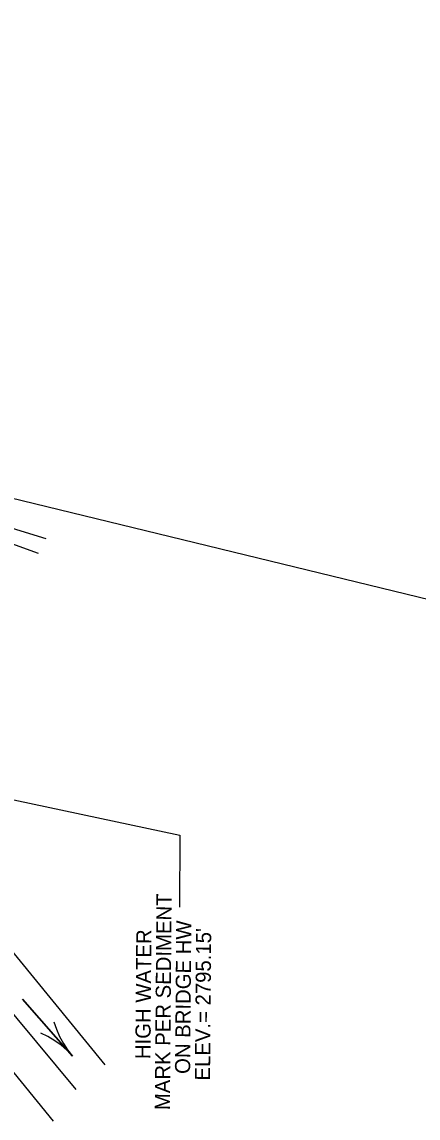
# Model space of a CAD drawing. Extents: x 1088366 to 1089341, y 781245 to 782648.
# Drawn here: x 1088931.9 to 1089036.3, y 781554.6 to 781843.2 of the extents above; entities that cross this region are included whole.
import ezdxf

# ---------------------------------------------------------------- set-up
doc = ezdxf.new("R2010")
doc.units = 0
for name, color, linetype in [('Exist DTM Spot Elevation Leader', 7, 'Continuous'), ('Exist DTM Spot Elevation Text', 7, 'Continuous'), ('Exist Hydro Jurisdictional Stream or Body of Water', 7, 'Continuous'), ('Exist Hydro River Flow Arrow CELL', 7, 'Continuous'), ('Exist Property Line', 7, 'Continuous'), ('Exist Roads Soil', 7, 'Continuous'), ('Exist Vegetation Woods Line', 7, 'Continuous')]:
    doc.layers.add(name, color=color, linetype=linetype)

msp = doc.modelspace()

# ---------------------------------------------------------------- linework, layer by layer
at = {"layer": 'Exist DTM Spot Elevation Leader'}
msp.add_lwpolyline([(1088869.43, 781651.14), (1088973.58, 781629.08), (1088973.42, 781610.13)], dxfattribs=at)
at = {"layer": 'Exist Hydro Jurisdictional Stream or Body of Water'}
for points in [[(1088953.84, 781568.58), (1088926.46, 781602.12), (1088911.94, 781623.53), (1088894.24, 781650), (1088883.33, 781666.95), (1088869.26, 781670.6), (1088867.16, 781672.95)], [(1088946.2, 781562.04), (1088920.23, 781593.24), (1088897.39, 781620.42), (1088884.95, 781640.8), (1088873.35, 781653.24), (1088866.79, 781656.11)]]:
    msp.add_lwpolyline(points, dxfattribs=at)
at = {"layer": 'Exist Hydro River Flow Arrow CELL'}
msp.add_line((1088938.67, 781578.4), (1088938.67, 781578.4), dxfattribs=at)
msp.add_lwpolyline([(1088940.38, 781579.91), (1088941.04, 781577.97), (1088941.87, 781576.07), (1088942.86, 781574.22), (1088943.98, 781572.48), (1088945.28, 781570.89), (1088932.06, 781585.9), (1088945.28, 781570.89), (1088943.87, 781572.38), (1088942.28, 781573.71), (1088940.57, 781574.93), (1088938.79, 781575.99), (1088936.95, 781576.88)], dxfattribs=at)
at = {"layer": 'Exist Property Line'}
msp.add_line((1088887.78, 781727.92), (1089277.34, 781633.17), dxfattribs=at)
at = {"layer": 'Exist Roads Soil'}
msp.add_lwpolyline([(1088936.3, 781703.23), (1088910.86, 781712.46), (1088894.35, 781716.45), (1088880.49, 781722.78), (1088873.17, 781728.87), (1088868.09, 781739.51)], dxfattribs=at)
at = {"layer": 'Exist Vegetation Woods Line'}
for points in [[(1088938.32, 781707.06), (1088898.21, 781719.36), (1088881.24, 781725.94), (1088868.09, 781739.51), (1088882.14, 781907.48)], [(1088992.73, 781306.05), (1088897.1, 781404.36), (1088893.35, 781443.24), (1088904.2, 781521.06), (1088876.71, 781575.21), (1088876.03, 781632.36), (1088940.16, 781553.71)]]:
    msp.add_lwpolyline(points, dxfattribs=at)

# ---------------------------------------------------------------- texts
at = {"layer": 'Exist DTM Spot Elevation Text'}
for s, p in [('MARK PER SEDIMENT', (1088970.93, 781556.63)), ('ON BRIDGE HW', (1088976.26, 781566.16)), ('HIGH WATER', (1088965.79, 781570.06)), ("ELEV.= 2795.15'", (1088981.5, 781564.42))]:
    msp.add_text(s, height=4, rotation=89.533, dxfattribs=at).set_placement(p)

doc.saveas('drawing.dxf')
